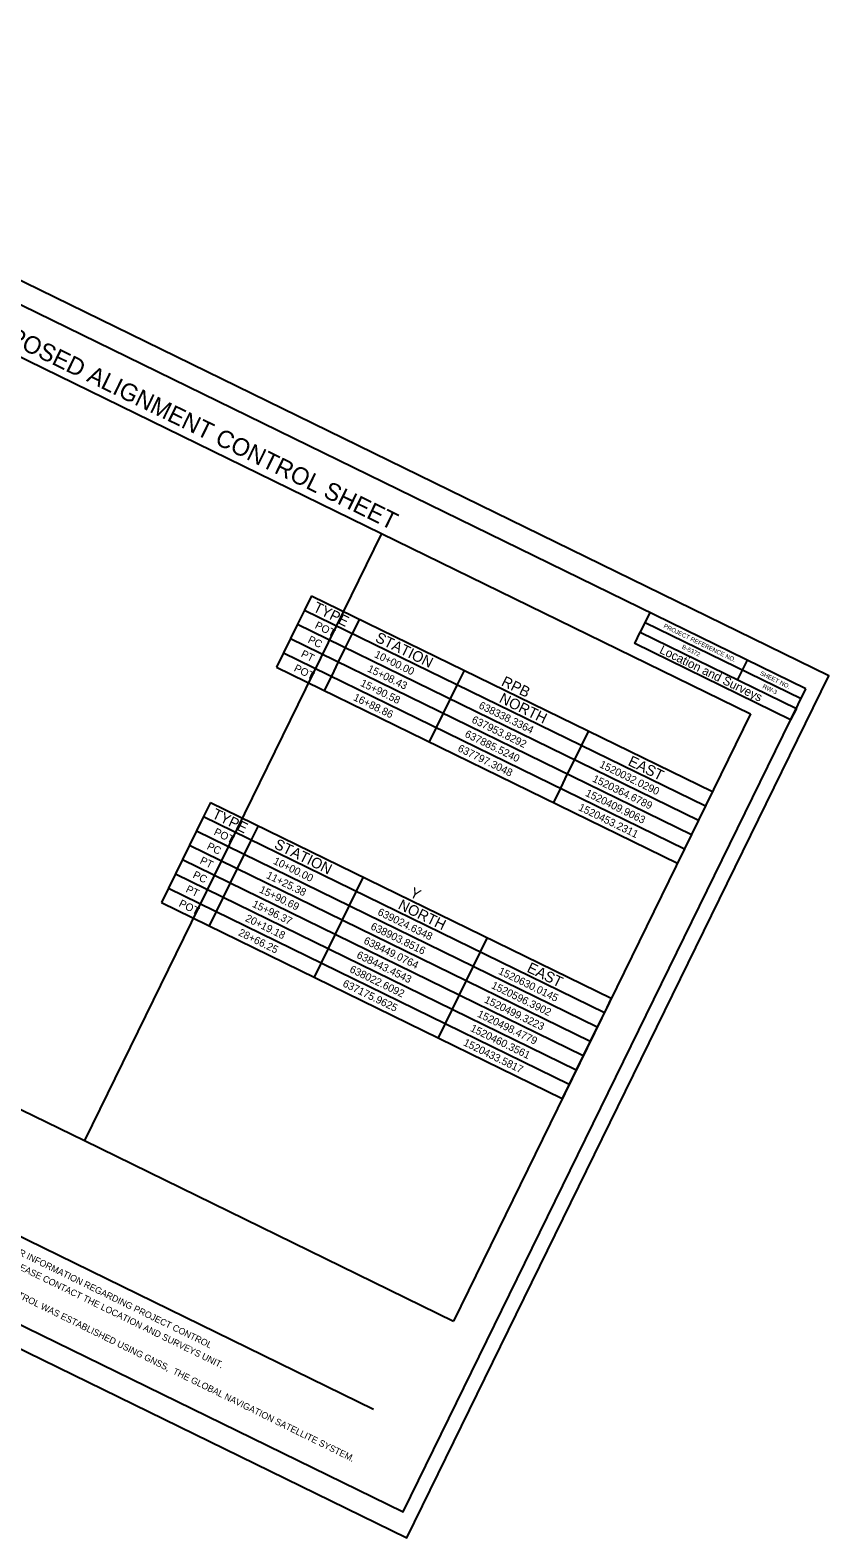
# Model space of a CAD drawing. Extents: x 1523259 to 1525268, y 635471 to 637211.
# Drawn here: x 1524347 to 1525268, y 635471 to 637211 of the extents above; entities that cross this region are included whole.
import ezdxf

# ---------------------------------------------------------------- set-up
doc = ezdxf.new("R2010")
doc.units = 0
for name, color, linetype in [('CTL Sheet Border CELL', 7, 'Continuous'), ('CTL Sheet Notes CELL', 7, 'Continuous'), ('CTL Sheet Table Cell', 7, 'Continuous'), ('CTL Sheet Text', 7, 'Continuous'), ('Scratch_Level_3', 7, 'Continuous'), ('Sheet Plot Border Outside CELL', 7, 'Continuous')]:
    doc.layers.add(name, color=color, linetype=linetype)

msp = doc.modelspace()

# ---------------------------------------------------------------- linework, layer by layer
at = {"layer": 'CTL Sheet Border CELL'}
for p, q in [((1525061.7, 636538.9), (1525050.7, 636516.3)), ((1525056.2, 636527.6), (1525236.1, 636439.6)), ((1525173.8, 636484.1), (1525162.7, 636461.5)), ((1525268.1, 636466), (1525268.1, 636466)), ((1525254.1, 636447.7), (1525254.1, 636447.7)), ((1525254.1, 636447.7), (1525254.1, 636447.7))]:
    msp.add_line(p, q, dxfattribs=at)
for points in [[(1525241.6, 636451), (1523885.2, 637114.4), (1523420.8, 636164.9), (1524777.2, 635501.4)], [(1525050.7, 636516.3), (1525230.6, 636428.3), (1525224, 636415), (1525044.2, 636503)]]:
    msp.add_lwpolyline(points, close=True, dxfattribs=at)
at = {"layer": 'CTL Sheet Notes CELL'}
msp.add_line((1524266.2, 635853.1), (1524743.2, 635619.8), dxfattribs=at)
at = {"layer": 'CTL Sheet Table Cell'}
for p, q in [((1524671.6, 636558.3), (1524663.6, 636541.8)), ((1524671.6, 636558.3), (1525133.8, 636332.3)), ((1524663.6, 636541.8), (1524655.5, 636525.3)), ((1524663.6, 636541.8), (1525125.7, 636315.8)), ((1524726.7, 636531.4), (1524718.6, 636514.9)), ((1524655.5, 636525.3), (1524647.4, 636508.8)), ((1524655.5, 636525.3), (1525117.7, 636299.3)), ((1524718.6, 636514.9), (1524710.5, 636498.4)), ((1524647.4, 636508.8), (1524639.3, 636492.3)), ((1524647.4, 636508.8), (1525109.6, 636282.8)), ((1524710.5, 636498.4), (1524702.4, 636481.9)), ((1524639.3, 636492.3), (1524631.3, 636475.8)), ((1524639.3, 636492.3), (1525101.5, 636266.3)), ((1524702.4, 636481.9), (1524694.4, 636465.4)), ((1524631.3, 636475.8), (1525093.5, 636249.8)), ((1524694.4, 636465.4), (1524686.3, 636448.9)), ((1524847.7, 636472.2), (1524839.6, 636455.7)), ((1524839.6, 636455.7), (1524831.6, 636439.2)), ((1524831.6, 636439.2), (1524823.5, 636422.7)), ((1524823.5, 636422.7), (1524815.4, 636406.2)), ((1524815.4, 636406.2), (1524807.3, 636389.7)), ((1524990.8, 636402.3), (1524982.7, 636385.8)), ((1524982.7, 636385.8), (1524974.6, 636369.2)), ((1524974.6, 636369.2), (1524966.5, 636352.7)), ((1524966.5, 636352.7), (1524958.5, 636336.2)), ((1524555, 636319.9), (1524547, 636303.4)), ((1524555, 636319.9), (1525017.2, 636093.9)), ((1524958.5, 636336.2), (1524950.4, 636319.7)), ((1525133.8, 636332.3), (1525125.7, 636315.8)), ((1524547, 636303.4), (1524538.9, 636286.9)), ((1524547, 636303.4), (1525009.2, 636077.4)), ((1525125.7, 636315.8), (1525117.7, 636299.3)), ((1524538.9, 636286.9), (1524530.8, 636270.4)), ((1524538.9, 636286.9), (1525001.1, 636060.9)), ((1524610.1, 636293), (1524602, 636276.5)), ((1525117.7, 636299.3), (1525109.6, 636282.8)), ((1524530.8, 636270.4), (1524522.8, 636253.9)), ((1524530.8, 636270.4), (1524993, 636044.4)), ((1524602, 636276.5), (1524593.9, 636260)), ((1525109.6, 636282.8), (1525101.5, 636266.3)), ((1524522.8, 636253.9), (1524514.7, 636237.4)), ((1524522.8, 636253.9), (1524984.9, 636027.9)), ((1524593.9, 636260), (1524585.8, 636243.5)), ((1525101.5, 636266.3), (1525093.5, 636249.8)), ((1524514.7, 636237.4), (1524506.6, 636220.9)), ((1524514.7, 636237.4), (1524976.9, 636011.4)), ((1524585.8, 636243.5), (1524577.8, 636227)), ((1524731.1, 636233.8), (1524723, 636217.3)), ((1524506.6, 636220.9), (1524498.5, 636204.4)), ((1524506.6, 636220.9), (1524968.8, 635994.9)), ((1524577.8, 636227), (1524569.7, 636210.5)), ((1524723, 636217.3), (1524715, 636200.8)), ((1524498.5, 636204.4), (1524960.7, 635978.4)), ((1524569.7, 636210.5), (1524561.6, 636194)), ((1524715, 636200.8), (1524706.9, 636184.3)), ((1524561.6, 636194), (1524553.6, 636177.5)), ((1524706.9, 636184.3), (1524698.8, 636167.8)), ((1524698.8, 636167.8), (1524690.7, 636151.3)), ((1524874.2, 636163.9), (1524866.1, 636147.4)), ((1524690.7, 636151.3), (1524682.7, 636134.8)), ((1524866.1, 636147.4), (1524858, 636130.9)), ((1524682.7, 636134.8), (1524674.6, 636118.3)), ((1524858, 636130.9), (1524850, 636114.4)), ((1524850, 636114.4), (1524841.9, 636097.8)), ((1524841.9, 636097.8), (1524833.8, 636081.3)), ((1525017.2, 636093.9), (1525009.2, 636077.4)), ((1524833.8, 636081.3), (1524825.7, 636064.8)), ((1525009.2, 636077.4), (1525001.1, 636060.9)), ((1524825.7, 636064.8), (1524817.7, 636048.3)), ((1525001.1, 636060.9), (1524993, 636044.4)), ((1524993, 636044.4), (1524984.9, 636027.9)), ((1524984.9, 636027.9), (1524976.9, 636011.4)), ((1524976.9, 636011.4), (1524968.8, 635994.9)), ((1524968.8, 635994.9), (1524960.7, 635978.4))]:
    msp.add_line(p, q, dxfattribs=at)
at = {"layer": 'Scratch_Level_3'}
for p, q in [((1524327, 636838.2), (1524752.4, 636630.2)), ((1524752.4, 636630.2), (1524409.7, 635929.6)), ((1524752.4, 636630.2), (1525177.8, 636422.1)), ((1525177.8, 636422.1), (1524835.1, 635721.5)), ((1523984.4, 636137.6), (1524409.7, 635929.6)), ((1524409.7, 635929.6), (1524835.1, 635721.5))]:
    msp.add_line(p, q, dxfattribs=at)
at = {"layer": 'Sheet Plot Border Outside CELL'}
msp.add_lwpolyline([(1523258.7, 636216.1), (1524781.6, 635471.3), (1525268.1, 636466), (1523745.2, 637210.8)], close=True, dxfattribs=at)

# ---------------------------------------------------------------- texts
at = {"layer": 'CTL Sheet Border CELL'}
for s, height, p in [('PROPOSED ALIGNMENT CONTROL SHEET', 20.133, (1524267.3, 636876.7)), ('PROJECT REFERENCE NO.', 5.033, (1525077, 636521.7)), ('Location and Surveys', 10.067, (1525072, 636492.6)), ('B-5372', 5.03, (1525098.2, 636497.6)), ('SHEET NO.', 5.03, (1525188.3, 636467.2)), ('RW-3', 5.03, (1525191.1, 636452))]:
    msp.add_text(s, height=height, rotation=333.9377, dxfattribs=at).set_placement(p)
at = {"layer": 'CTL Sheet Notes CELL'}
for s, height, rotation, p in [('TYPE', 12.25, 333.9377, (1524672.4, 636540.9)), ('STATION', 12.25, 333.9377, (1524744.1, 636505.9)), ('RPB', 12.25, 333.9377, (1524889.5, 636455.2)), ('NORTH', 12.25, 333.9377, (1524887, 636435.9)), ('EAST', 12.25, 333.9377, (1525035.5, 636363.3)), ('TYPE', 12.25, 333.9377, (1524555.8, 636302.5)), ('STATION', 12.25, 333.9377, (1524627.5, 636267.5)), ('Y', 12.3, 333.9377, (1524783.8, 636211.5)), ('NORTH', 12.25, 333.9377, (1524770.4, 636197.6)), ('EAST', 12.25, 333.9377, (1524919, 636124.9)), ('IS NEEDED, PLEASE CONTACT THE LOCATION AND SURVEYS UNIT.', 7.55, 333.9377, (1524269, 635812.7)), ('1. IF FURTHER INFORMATION REGARDING PROJECT CONTROL', 7.55, 333.9377, (1524275.6, 635826.1)), ('2. PROJECT CONTROL WAS ESTABLISHED USING GNSS,  THE GLOBAL NAVIGATION SATELLITE SYSTEM.', 7.548, 333.8325, (1524256.7, 635785.8))]:
    msp.add_text(s, height=height, rotation=rotation, dxfattribs=at).set_placement(p)
at = {"layer": 'CTL Sheet Text'}
for s, p in [('POT', (1524674.7, 636521.3)), ('PC ', (1524666.6, 636504.8)), ('PT ', (1524658.6, 636488.3)), ('10+00.00', (1524743.3, 636487.8)), ('POT', (1524650.5, 636471.8)), ('15+08.43', (1524735.2, 636471.3)), ('15+90.58', (1524727.1, 636454.7)), ('16+88.86', (1524719, 636438.2)), ('638338.3364', (1524863.6, 636428.9)), ('637953.8292', (1524855.5, 636412.4)), ('637885.5240', (1524847.5, 636395.9)), ('637797.3048', (1524839.4, 636379.4)), ('1520032.0290', (1525002.8, 636360.8)), ('1520364.6789', (1524994.7, 636344.3)), ('1520409.9063', (1524986.6, 636327.8)), ('1520453.2311', (1524978.5, 636311.3)), ('POT', (1524558.1, 636282.9)), ('PC ', (1524550.1, 636266.4)), ('PT ', (1524542, 636249.9)), ('10+00.00', (1524626.7, 636249.4)), ('PC ', (1524533.9, 636233.4)), ('11+25.38', (1524618.6, 636232.9)), ('PT ', (1524525.8, 636216.9)), ('15+90.69', (1524610.5, 636216.4)), ('POT', (1524517.8, 636200.4)), ('15+96.37', (1524602.4, 636199.8)), ('20+19.18', (1524594.4, 636183.3)), ('638903.8516', (1524738.9, 636174)), ('639024.6348', (1524747, 636190.5)), ('28+66.25', (1524586.3, 636166.8)), ('638449.0764', (1524730.9, 636157.5)), ('638443.4543', (1524722.8, 636141)), ('638022.6092', (1524714.7, 636124.5)), ('1520630.0145', (1524886.2, 636122.4)), ('637175.9625', (1524706.7, 636108)), ('1520596.3902', (1524878.1, 636105.9)), ('1520499.3223', (1524870, 636089.4)), ('1520498.4779', (1524862, 636072.9)), ('1520460.3561', (1524853.9, 636056.4)), ('1520433.5817', (1524845.8, 636039.9))]:
    msp.add_text(s, height=8.75, rotation=333.9377, dxfattribs=at).set_placement(p)

doc.saveas('drawing.dxf')
